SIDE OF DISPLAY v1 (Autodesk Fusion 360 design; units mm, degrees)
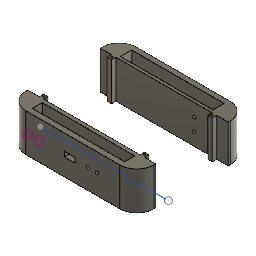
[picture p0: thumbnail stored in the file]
sketch "3D PRINT" plane through (-0.8791, 0, 12.2444) normal (0, 1, 0) x axis (1, 0, 0)
  curve K1 (-136.7026, -1.6283) -> (-136.7037, -1.717)
  curve K2 (-109.8608, 25.1704) -> (-136.7026, -1.6283)
  line L1 (37.4702, 25.1704) -> (-109.8608, 25.1704)
  curve K3 (64.3131, -1.7057) -> (37.4702, 25.1704)
  line L2 (64.3132, -1.717) -> (64.3131, -1.7057)
  line L3 (-136.7037, -1.717) -> (64.3132, -1.717)
  curve K4 (-136.7035, -21.1949) -> (-136.7035, -21.1949)
  curve K5 (37.4704, -48.0823) -> (64.3134, -21.1949)
  line L4 (-109.8606, -48.0823) -> (37.4704, -48.0823)
  curve K6 (-136.7035, -21.1949) -> (-109.8606, -48.0823)
  line L5 (64.3134, -21.1949) -> (-136.7035, -21.1949)
  curve K7 (64.3134, -21.1949) -> (64.3134, -21.1949)
sketch "Sketch2" plane through (0, 0, 0) normal (0, 1, 0) x axis (1, 0, 0)
extrude "Extrude1" new body sketch "3D PRINT" profile of K1 K2 L1 K3 L2 L3 K5 L4 K6 L5 along normal blind 60
move "Move1"
sketch "Sketch3" plane through (0, 0, 160.3267) normal (0, 0, 1) x axis (1, 0, 0)
  line L1 (36.5913, 0) -> (-110.7397, 0)
  line L2 (36.5913, 60) -> (36.5913, 0)
  line L3 (-110.7397, 60) -> (36.5913, 60)
  line L4 (-110.7397, 0) -> (-110.7397, 60)
  line L5 (-33.5, 35) -> (-50, 35)
  line L6 (-33.5, 27.5) -> (-33.5, 35)
  line L7 (-50, 27.5) -> (-33.5, 27.5)
  line L8 (-50, 35) -> (-50, 27.5)
  circle C1 centre (-13.3876, 31.25) radius 2.5
  circle C2 centre (0.6124, 31.25) radius 2.5
  point P6 (-50, 35)
  point P7 (-33.5, 35)
  point P9 (-50, 27.5)
  dimension "d3" distance P6 P7 = 16.5
  dimension "d4" distance P6 P9 = 7.5
  dimension "d5" diameter C1 = 5
  dimension "d6" diameter C2 = 5
extrude "Extrude2" cut sketch "Sketch3" profile of L5 L6 L7 L8 C1 C2 against normal blind 80
sketch "Sketch4" plane through (0, 0, -12.926) normal (0, 0, -1) x axis (-1, 0, 0)
  line L1 (110.7399, 0) -> (-36.5911, 0)
  line L2 (110.7399, 60) -> (110.7399, 0)
  line L3 (-36.5911, 60) -> (110.7399, 60)
  line L4 (-36.5911, 0) -> (-36.5911, 60)
  circle C1 centre (-10, 40) radius 2.5
  circle C2 centre (-10, 20) radius 2.5
  dimension "d9" diameter C1 = 5
  dimension "d10" diameter C2 = 5
extrude "Extrude3" cut sketch "Sketch4" profile of C1 C2 against normal blind 110
extrude "Extrude4" add of existing geometry blind 3
extrude "Extrude5" add of existing geometry blind 3
sketch "Sketch5" plane through (0, 0, 16.9614) normal (0, 0, 1) x axis (1, 0, 0)
  line L1 (63.4341, 0) -> (-137.5828, 0)
  line L2 (63.4341, 60) -> (63.4341, 0)
  line L3 (-137.5828, 60) -> (63.4341, 60)
  line L4 (-112.5828, 60) -> (-119.5828, 60)
  line L5 (-112.5828, 0) -> (-112.5828, 60)
  line L6 (-119.5828, 0) -> (-112.5828, 0)
  line L7 (-119.5828, 60) -> (-119.5828, 0)
  circle C1 centre (10, 40) radius 2.5
  circle C2 centre (10, 20) radius 2.5
  point P7 (-137.5828, 60)
  point P8 (-119.5828, 60)
  point P9 (-112.5828, 60)
  dimension "d17" distance P7 P8 = 18
  dimension "d18" distance P8 P9 = 7
extrude "Extrude6" add sketch "Sketch5" profile of L1 L3 L4 L5 L6 L7 along normal blind 7
sketch "Sketch6" plane through (0, 0, 23.9614) normal (0, 0, 1) x axis (1, 0, 0)
  line L1 (-112.5828, 0) -> (-119.5828, 0)
  line L2 (-112.5828, 60) -> (-112.5828, 0)
  line L3 (-119.5828, 60) -> (-112.5828, 60)
  line L4 (-119.5828, 0) -> (-119.5828, 60)
sketch "Sketch7" plane through (0, 0, 0) normal (0, -1, 0) x axis (1, 0, 0)
  line L1 (63.4341, 13.9614) -> (63.434, 13.9501)
  line L2 (63.4341, 16.9614) -> (63.4341, 13.9614)
  line L3 (-112.5828, 16.9614) -> (63.4341, 16.9614)
  line L4 (-112.5828, 23.9614) -> (-112.5828, 16.9614)
  line L5 (-119.5828, 23.9614) -> (-112.5828, 23.9614)
  line L6 (-119.5828, 16.9614) -> (-119.5828, 23.9614)
  line L7 (-137.5828, 16.9614) -> (-119.5828, 16.9614)
  line L8 (-137.5828, 13.9614) -> (-137.5828, 16.9614)
  curve K1 (-137.5817, 13.8727) -> (-137.5828, 13.9614)
  curve K2 (-110.7399, -12.926) -> (-137.5817, 13.8727)
  line L9 (36.5911, -12.926) -> (-110.7399, -12.926)
  curve K3 (63.434, 13.9501) -> (36.5911, -12.926)
  circle C1 centre (-116, 20) radius 1.5
  dimension "d21" diameter C1 = 3
extrude "Extrude7" cut sketch "Sketch7" profile of C1 against normal blind 65
sketch "Sketch8" plane through (0, 0, 16.9614) normal (0, 0, 1) x axis (1, 0, 0)
  line L1 (-112.5828, 0) -> (-112.5828, 60)
  line L2 (63.4341, 0) -> (-112.5828, 0)
  line L3 (63.4341, 60) -> (63.4341, 0)
  line L4 (-112.5828, 60) -> (63.4341, 60)
  line L5 (38.4341, 60) -> (45.4341, 60)
  line L6 (38.4341, 0) -> (38.4341, 60)
  line L7 (45.4341, 0) -> (38.4341, 0)
  line L8 (45.4341, 60) -> (45.4341, 0)
  circle C1 centre (10, 20) radius 2.5
  circle C2 centre (10, 40) radius 2.5
  point P5 (63.4341, 60)
  point P8 (45.4341, 60)
  point P9 (38.4341, 60)
  dimension "d25" distance P5 P8 = 18
  dimension "d26" distance P8 P9 = 7
extrude "Extrude8" add sketch "Sketch8" profile of L2 L4 L5 L6 L7 L8 along normal blind 7
sketch "Sketch9" plane through (0, 0, 0) normal (0, -1, 0) x axis (1, 0, 0)
  line L1 (63.4341, 13.9614) -> (63.434, 13.9501)
  line L2 (63.4341, 16.9614) -> (63.4341, 13.9614)
  line L3 (45.4341, 16.9614) -> (63.4341, 16.9614)
  line L4 (45.4341, 23.9614) -> (45.4341, 16.9614)
  line L5 (38.4341, 23.9614) -> (45.4341, 23.9614)
  line L6 (38.4341, 16.9614) -> (38.4341, 23.9614)
  line L7 (-112.5828, 16.9614) -> (38.4341, 16.9614)
  line L8 (-112.5828, 23.9614) -> (-112.5828, 16.9614)
  line L9 (-119.5828, 23.9614) -> (-112.5828, 23.9614)
  line L10 (-119.5828, 16.9614) -> (-119.5828, 23.9614)
  line L11 (-137.5828, 16.9614) -> (-119.5828, 16.9614)
  line L12 (-137.5828, 13.9614) -> (-137.5828, 16.9614)
  curve K1 (-137.5817, 13.8727) -> (-137.5828, 13.9614)
  curve K2 (-110.7399, -12.926) -> (-137.5817, 13.8727)
  line L13 (36.5911, -12.926) -> (-110.7399, -12.926)
  curve K3 (63.434, 13.9501) -> (36.5911, -12.926)
  circle C1 centre (-116, 20) radius 1.5
  circle C2 centre (41.6703, 20.4614) radius 1.5
  dimension "d29" diameter C2 = 3
extrude "Extrude9" cut sketch "Sketch9" profile of C2 against normal blind 65
sketch "Sketch10" plane through (0, 0, 130.4393) normal (0, 0, -1) x axis (-1, 0, 0)
  line L1 (33.5, 35) -> (33.5, 27.5)
  line L2 (50, 35) -> (33.5, 35)
  line L3 (50, 27.5) -> (50, 35)
  line L4 (33.5, 27.5) -> (50, 27.5)
  line L5 (137.5826, 0) -> (-63.4343, 0)
  line L6 (137.5826, 60) -> (137.5826, 0)
  line L7 (-63.4343, 60) -> (137.5826, 60)
  line L8 (-63.4343, 0) -> (-63.4343, 60)
  line L9 (119.5826, 60) -> (137.5826, 60)
  line L10 (119.5826, 0) -> (119.5826, 60)
  line L11 (137.5826, 0) -> (119.5826, 0)
  line L12 (137.5826, 60) -> (137.5826, 0)
  line L13 (112.5826, 60) -> (119.5826, 60)
  line L14 (112.5826, 0) -> (112.5826, 60)
  line L15 (119.5826, 0) -> (112.5826, 0)
  line L16 (119.5826, 60) -> (119.5826, 0)
  circle C1 centre (13.3876, 31.25) radius 2.5
  circle C2 centre (-0.6124, 31.25) radius 2.5
  point P12 (137.5826, 60)
  point P15 (137.5826, 0)
  point P13 (119.5826, 60)
  point P18 (119.5826, 0)
  point P16 (112.5826, 60)
  dimension "d32" distance P12 P15 = 60
  dimension "d33" distance P12 P13 = 18
  dimension "d34" distance P13 P18 = 60
  dimension "d35" distance P13 P16 = 7
extrude "Extrude10" add sketch "Sketch10" profile of L5 L7 L10 L13 L14 L15 L16 along normal blind 7
sketch "Sketch11" plane through (0, 0, 130.4393) normal (0, 0, -1) x axis (-1, 0, 0)
  line L1 (112.5826, 60) -> (112.5826, 0)
  line L2 (-63.4343, 60) -> (112.5826, 60)
  line L3 (-63.4343, 0) -> (-63.4343, 60)
  line L4 (112.5826, 0) -> (-63.4343, 0)
  line L5 (33.5, 35) -> (33.5, 27.5)
  line L6 (50, 35) -> (33.5, 35)
  line L7 (50, 27.5) -> (50, 35)
  line L8 (33.5, 27.5) -> (50, 27.5)
  line L9 (-45.4343, 60) -> (-63.4343, 60)
  line L10 (-45.4343, 0) -> (-45.4343, 60)
  line L11 (-63.4343, 0) -> (-45.4343, 0)
  line L12 (-63.4343, 60) -> (-63.4343, 0)
  line L13 (-38.4343, 60) -> (-45.4343, 60)
  line L14 (-38.4343, 0) -> (-38.4343, 60)
  line L15 (-45.4343, 0) -> (-38.4343, 0)
  line L16 (-45.4343, 60) -> (-45.4343, 0)
  circle C1 centre (13.3876, 31.25) radius 2.5
  circle C2 centre (-0.6124, 31.25) radius 2.5
  point P12 (-63.4343, 60)
  point P13 (-45.4343, 60)
  point P16 (-38.4343, 60)
  dimension "d38" distance P12 P13 = 18
  dimension "d39" distance P13 P16 = 7
extrude "Extrude11" add sketch "Sketch11" profile of L2 L4 L10 L13 L14 L15 L16 along normal blind 7
sketch "Sketch12" plane through (0, 0, 0) normal (0, -1, 0) x axis (1, 0, 0)
  curve K1 (-137.5826, 133.4393) -> (-110.7397, 160.3267)
  line L1 (-137.5826, 130.4393) -> (-137.5826, 133.4393)
  line L2 (-119.5826, 130.4393) -> (-137.5826, 130.4393)
  line L3 (-119.5826, 123.4393) -> (-119.5826, 130.4393)
  line L4 (-112.5826, 123.4393) -> (-119.5826, 123.4393)
  line L5 (-112.5826, 130.4393) -> (-112.5826, 123.4393)
  line L6 (38.4343, 130.4393) -> (-112.5826, 130.4393)
  line L7 (38.4343, 123.4393) -> (38.4343, 130.4393)
  line L8 (45.4343, 123.4393) -> (38.4343, 123.4393)
  line L9 (45.4343, 130.4393) -> (45.4343, 123.4393)
  line L10 (63.4343, 130.4393) -> (45.4343, 130.4393)
  line L11 (63.4343, 133.4393) -> (63.4343, 130.4393)
  curve K2 (36.5913, 160.3267) -> (63.4343, 133.4393)
  line L12 (-110.7397, 160.3267) -> (36.5913, 160.3267)
  circle C1 centre (41.7328, 126.9393) radius 1.5
  dimension "d42" diameter C1 = 3
extrude "Extrude12" cut sketch "Sketch12" profile of C1 against normal blind 95
sketch "Sketch13" plane through (0, 0, 0) normal (0, -1, 0) x axis (1, 0, 0)
  curve K1 (-137.5826, 133.4393) -> (-110.7397, 160.3267)
  line L1 (-137.5826, 130.4393) -> (-137.5826, 133.4393)
  line L2 (-119.5826, 130.4393) -> (-137.5826, 130.4393)
  line L3 (-119.5826, 123.4393) -> (-119.5826, 130.4393)
  line L4 (-112.5826, 123.4393) -> (-119.5826, 123.4393)
  line L5 (-112.5826, 130.4393) -> (-112.5826, 123.4393)
  line L6 (38.4343, 130.4393) -> (-112.5826, 130.4393)
  line L7 (38.4343, 123.4393) -> (38.4343, 130.4393)
  line L8 (45.4343, 123.4393) -> (38.4343, 123.4393)
  line L9 (45.4343, 130.4393) -> (45.4343, 123.4393)
  line L10 (63.4343, 130.4393) -> (45.4343, 130.4393)
  line L11 (63.4343, 133.4393) -> (63.4343, 130.4393)
  curve K2 (36.5913, 160.3267) -> (63.4343, 133.4393)
  line L12 (-110.7397, 160.3267) -> (36.5913, 160.3267)
  circle C1 centre (41.7328, 126.9393) radius 1.5
  circle C2 centre (-116.3457, 126.9393) radius 1.5
  dimension "d45" diameter C2 = 3
extrude "Extrude13" cut sketch "Sketch13" profile of C2 against normal blind 120
sketch "Sketch14" plane through (0, 60, 0) normal (0, 1, 0) x axis (-1, 0, 0)
  curve K1 (110.7397, 160.3267) -> (137.5826, 133.4393)
  line L1 (-36.5913, 160.3267) -> (110.7397, 160.3267)
  curve K2 (-63.4343, 133.4393) -> (-36.5913, 160.3267)
  line L2 (-63.4343, 130.4393) -> (-63.4343, 133.4393)
  line L3 (-45.4343, 130.4393) -> (-63.4343, 130.4393)
  line L4 (-45.4343, 123.4393) -> (-45.4343, 130.4393)
  line L5 (-38.4343, 123.4393) -> (-45.4343, 123.4393)
  line L6 (-38.4343, 130.4393) -> (-38.4343, 123.4393)
  line L7 (112.5826, 130.4393) -> (-38.4343, 130.4393)
  line L8 (112.5826, 123.4393) -> (112.5826, 130.4393)
  line L9 (119.5826, 123.4393) -> (112.5826, 123.4393)
  line L10 (119.5826, 130.4393) -> (119.5826, 123.4393)
  line L11 (137.5826, 130.4393) -> (119.5826, 130.4393)
  line L12 (137.5826, 133.4393) -> (137.5826, 130.4393)
  line L13 (-36.2278, 136.417) -> (108.8928, 136.417)
  line L14 (-36.2278, 152.1152) -> (-36.2278, 136.417)
  line L15 (108.8928, 152.1152) -> (-36.2278, 152.1152)
  line L16 (108.8928, 136.417) -> (108.8928, 152.1152)
  circle C1 centre (116.3457, 126.9393) radius 1.5
  circle C2 centre (-41.7328, 126.9393) radius 1.5
extrude "Extrude14" cut sketch "Sketch14" profile of L13 L14 L15 L16 against normal blind 910
sketch "Sketch15" plane through (0, 60, 0) normal (0, 1, 0) x axis (-1, 0, 0)
  line L1 (-63.434, 13.9501) -> (-63.4341, 13.9614)
  curve K1 (-36.5911, -12.926) -> (-63.434, 13.9501)
  line L2 (110.7399, -12.926) -> (-36.5911, -12.926)
  curve K2 (137.5817, 13.8727) -> (110.7399, -12.926)
  curve K3 (137.5828, 13.9614) -> (137.5817, 13.8727)
  line L3 (137.5828, 16.9614) -> (137.5828, 13.9614)
  line L4 (119.5828, 16.9614) -> (137.5828, 16.9614)
  line L5 (119.5828, 23.9614) -> (119.5828, 16.9614)
  line L6 (112.5828, 23.9614) -> (119.5828, 23.9614)
  line L7 (112.5828, 16.9614) -> (112.5828, 23.9614)
  line L8 (-38.4341, 16.9614) -> (112.5828, 16.9614)
  line L9 (-38.4341, 23.9614) -> (-38.4341, 16.9614)
  line L10 (-45.4341, 23.9614) -> (-38.4341, 23.9614)
  line L11 (-45.4341, 16.9614) -> (-45.4341, 23.9614)
  line L12 (-63.4341, 16.9614) -> (-45.4341, 16.9614)
  line L13 (-63.4341, 13.9614) -> (-63.4341, 16.9614)
  line L14 (-35.0103, -5.0507) -> (110.1103, -5.0507)
  line L15 (-35.0103, 12.5421) -> (-35.0103, -5.0507)
  line L16 (110.1103, 12.5421) -> (-35.0103, 12.5421)
  line L17 (110.1103, -5.0507) -> (110.1103, 12.5421)
  circle C1 centre (-41.6703, 20.4614) radius 1.5
  circle C2 centre (116, 20) radius 1.5
  point P20 (110.1103, -5.0507)
  point P23 (110.1103, 12.5421)
  dimension "d50" distance P20 P23 = 17.5928
extrude "Extrude15" cut sketch "Sketch15" profile of L14 L15 L16 L17 against normal blind 1360
sketch "Sketch16" plane through (0, 0, 0) normal (0, 1, 0) x axis (1, 0, 0)
  line L1 (-137.5826, -130.4393) -> (-119.5826, -130.4393)
  line L2 (63.4343, -110.6984) -> (-137.5826, -110.6984)
  point P4 (-137.5826, -110.6984)
  point P5 (63.4343, -110.6984)
  dimension "d53" distance P4 P5 = 201.0169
